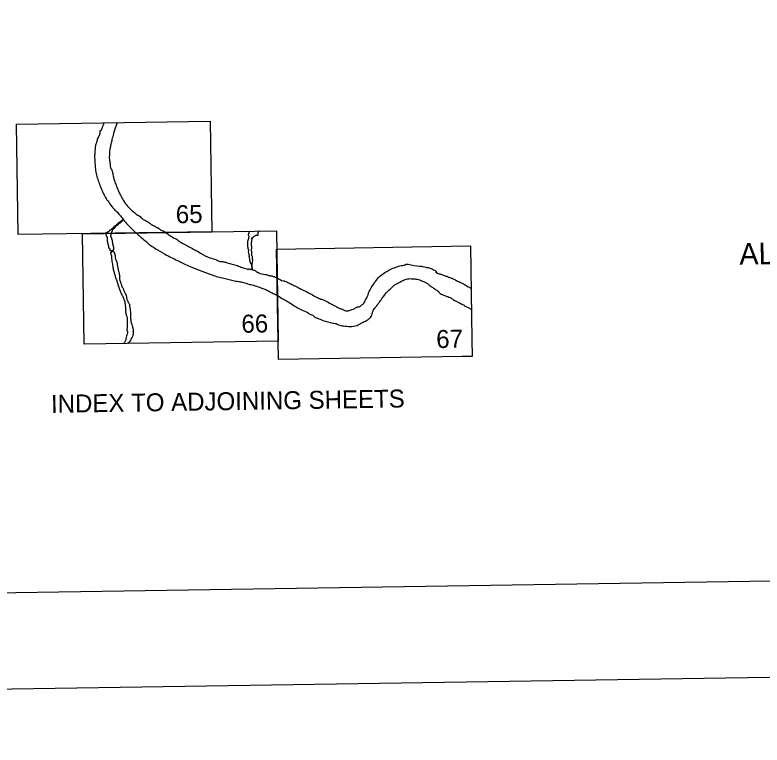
# Model space of a CAD drawing. Extents: x 3823584 to 3861785, y 301729 to 327625.
# Drawn here: x 3848300 to 3853151, y 302313 to 307056 of the extents above; entities that cross this region are included whole.
import ezdxf

# ---------------------------------------------------------------- set-up
doc = ezdxf.new("R2010")
doc.units = 0
for name, color, linetype in [('G-ANNO-NPLT', 7, 'Continuous'), ('V-ANNO-NPLT', 7, 'Continuous'), ('V-ANNO-SYMB', 7, 'Continuous'), ('V-ANNO-TEXT', 7, 'Continuous')]:
    doc.layers.add(name, color=color, linetype=linetype)

msp = doc.modelspace()

# ---------------------------------------------------------------- linework, layer by layer
at = {"layer": 'G-ANNO-NPLT'}
msp.add_lwpolyline([(3824539.5, 302312.7), (3861201.8, 302878), (3860829.2, 327041.8), (3824166.9, 326476.5)], close=True, dxfattribs=at)
at = {"layer": 'V-ANNO-NPLT'}
for points in [[(3848320, 305629), (3848309.4, 306347), (3849566.6, 306366.1), (3849577.8, 305648)], [(3849577.8, 305648), (3848320, 305629)], [(3848750, 304917.1), (3848739.2, 305635.2), (3849997, 305654.6), (3850008.4, 304936.5)], [(3850010.3, 304816.8), (3849998.9, 305534.9), (3851256.8, 305555.4), (3851267, 304947.3)], [(3850008.4, 304936.5), (3848750, 304917.1)], [(3851267, 304947.3), (3851268.8, 304837.3)], [(3851202.9, 304836.3), (3850010.3, 304816.8)], [(3851268.8, 304837.3), (3851202.9, 304836.3)]]:
    msp.add_lwpolyline(points, dxfattribs=at)
for points in [[(3848876.3, 306355.6), (3848870.6, 306335.7), (3848866.8, 306328.1), (3848859.7, 306307.2), (3848857.3, 306304.8), (3848853.5, 306303.3), (3848851.1, 306301), (3848850.2, 306293.3), (3848844, 306267.1), (3848841.6, 306263.3), (3848839.2, 306259), (3848831.1, 306233.3), (3848828.3, 306225.2)], [(3848963.6, 306356.9), (3848959.1, 306343.4), (3848950.6, 306321), (3848942.5, 306294.3), (3848932, 306254.7), (3848923.9, 306223.8), (3848921.6, 306213.3)], [(3848828.3, 306225.2), (3848824.5, 306216.1), (3848820.7, 306192.3), (3848818.7, 306154.7), (3848818.7, 306150.4)], [(3848921.8, 306214.5), (3848917.3, 306189.5), (3848915.4, 306181.8), (3848913.9, 306151.4)], [(3848835.4, 305996), (3848827.3, 306035.6), (3848823, 306073.7), (3848820.2, 306107), (3848818.7, 306150.4)], [(3848913.9, 306151.4), (3848913, 306117.5), (3848917.7, 306088.9), (3848923, 306058.4), (3848926.3, 306053.2), (3848934.9, 306026.5), (3848940.6, 305996.5)], [(3848835.4, 305996), (3848846.8, 305961.7), (3848861.1, 305924.6), (3848874.9, 305894.5), (3848892, 305863.6)], [(3848940.6, 305996.5), (3848947.7, 305972.2), (3848960.6, 305940.3), (3848972, 305911.2), (3848984.9, 305885), (3849002.9, 305853.1)], [(3848892, 305863.6), (3848913.9, 305832.1), (3848944.4, 305793.5), (3848964.9, 305774)], [(3849002.9, 305853.1), (3849018.2, 305828.8), (3849042.9, 305801.2), (3849066.7, 305778.8)], [(3848964.9, 305774), (3848984.9, 305750.2), (3849005.8, 305724.5), (3849031.5, 305694)], [(3849066.7, 305778.8), (3849088.6, 305759.7), (3849095.3, 305754.9), (3849097.6, 305754.9), (3849099.6, 305754.5), (3849123.3, 305735.9), (3849143.8, 305722.1), (3849161.9, 305712.5), (3849175.2, 305703)], [(3848934.8, 305670.7), (3848936.8, 305673.6), (3848940.6, 305676), (3848942.7, 305680.5), (3848945.1, 305682.6), (3848948.5, 305685.8), (3848950.9, 305687.3), (3848953.3, 305688.2), (3848956.2, 305689), (3848957.4, 305690.2), (3848959.6, 305693), (3848961, 305695), (3848963, 305697.1), (3848967.3, 305700.3), (3848969.2, 305703.1), (3848972.3, 305705.1), (3848974.7, 305707), (3848976.9, 305709.4), (3848980.5, 305711.3), (3848982.7, 305712.5), (3849001.8, 305729.3)], [(3848942.8, 305668.5), (3848945.4, 305671.9), (3848949.3, 305675.7), (3848951.7, 305678.8), (3848953.1, 305681.7), (3848956.5, 305685.1), (3848959.3, 305687.3), (3848962.1, 305689.5), (3848966.5, 305691.5), (3848969.4, 305693), (3848971.4, 305695.9), (3848972.6, 305698.8), (3848975.2, 305701.2), (3848976.2, 305701.9), (3848979.5, 305704.3), (3848982.7, 305706.5), (3848985.3, 305708), (3848987.5, 305709.2), (3849005.2, 305725.2)], [(3848901.7, 305647), (3848904.3, 305647.6), (3848909.6, 305650.5), (3848913.9, 305654.3), (3848917.1, 305657.7), (3848921.4, 305661.3), (3848926.2, 305663.9), (3848930.5, 305667.8), (3848933.2, 305669.5), (3848934.8, 305670.7)], [(3848930.9, 305595.6), (3848929.1, 305599), (3848928.6, 305601.6), (3848928.1, 305606.2), (3848927.4, 305608.4), (3848925.9, 305612), (3848924.5, 305614.6), (3848923.3, 305617.3), (3848923.1, 305622.1), (3848923.5, 305625.9), (3848923.5, 305628.8), (3848923.8, 305631.7), (3848923.8, 305631.9), (3848925.5, 305635.1), (3848928.1, 305639.4), (3848928.6, 305642.5), (3848928.4, 305643.7), (3848928.6, 305645.4), (3848930, 305646.9), (3848932, 305651.2), (3848932.4, 305655), (3848932.2, 305658.4), (3848933.9, 305659.8), (3848936, 305662.2), (3848938.2, 305664.7), (3848940.1, 305666.6), (3848942.8, 305668.5)], [(3849031.5, 305694), (3849055.3, 305670.1), (3849085.8, 305640.6)], [(3849175.2, 305703), (3849196.2, 305689.2), (3849199, 305688.2), (3849217.1, 305676.8), (3849223.8, 305673.5), (3849226.2, 305674), (3849232.3, 305671.1), (3849253.3, 305655.8), (3849261.4, 305653.5), (3849276.3, 305643.4)], [(3848899.9, 305593.2), (3848900.1, 305595.9), (3848899.9, 305597.3), (3848900.1, 305599.7), (3848900.8, 305602.3), (3848901.3, 305606.4), (3848900.1, 305612.5), (3848896.7, 305614.6), (3848895.5, 305617), (3848894.1, 305622.3), (3848893.1, 305625.9), (3848892.2, 305630), (3848893.1, 305631.7), (3848891.7, 305634.3), (3848890.7, 305635.8), (3848889.8, 305638.2), (3848891.9, 305641.1), (3848893.4, 305642.3), (3848897.7, 305644.4)], [(3848897.7, 305644.4), (3848901.2, 305646.9), (3848901.7, 305647)], [(3849085.8, 305640.6), (3849105.7, 305622.4), (3849135, 305598), (3849162.9, 305573.5), (3849190, 305552.6), (3849226.3, 305529.6), (3849284.9, 305496.1), (3849324.6, 305475.8), (3849365, 305456.3), (3849397.8, 305440.2), (3849436.8, 305422.8)], [(3849276.3, 305643.4), (3849298.8, 305627.3), (3849326.7, 305610.5), (3849354.6, 305594.5), (3849376.2, 305579.1), (3849411, 305560.3), (3849443.8, 305542.1), (3849475.2, 305526.8), (3849504.5, 305509.3)], [(3849819.9, 305613.9), (3849820, 305617.7), (3849817.9, 305623.3), (3849816.6, 305627.9), (3849817.1, 305631.9), (3849819, 305636.2), (3849820.3, 305638.7), (3849820.3, 305642.4), (3849820.3, 305646.2), (3849821.9, 305650.8), (3849822.4, 305651.8)], [(3849844.1, 305608.1), (3849845.8, 305610.7), (3849848.2, 305614.5), (3849851.7, 305616.4), (3849857.9, 305620.7), (3849862.5, 305624.1), (3849865.4, 305625.2), (3849868.4, 305626.6), (3849871.6, 305626), (3849875.4, 305626), (3849878.9, 305627.4), (3849879.7, 305629.8), (3849879.9, 305633.6), (3849879.1, 305637.3), (3849878.9, 305640.5), (3849880.2, 305644.8), (3849881.3, 305648.1), (3849883.7, 305650.2), (3849885.8, 305651.3), (3849888.4, 305652.8)], [(3848901.7, 305584.2), (3848900.8, 305589.4), (3848900.1, 305591.8), (3848899.9, 305593.2)], [(3848903.7, 305573.3), (3848902.8, 305576.8), (3848902, 305582.4), (3848901.7, 305584.2)], [(3848928.4, 305516.3), (3848928.2, 305519.4), (3848927.5, 305522.2), (3848926.3, 305523.9), (3848924.4, 305524.6), (3848922.2, 305524.4), (3848921.5, 305524.4), (3848920.5, 305524.4), (3848918.1, 305525.4), (3848917.4, 305526.1), (3848917.4, 305528.7), (3848917.7, 305532.1), (3848917.4, 305536), (3848914.5, 305537.6), (3848913.8, 305538.1), (3848912.4, 305539.6), (3848910.7, 305543.6), (3848909.5, 305548), (3848908.8, 305552.5), (3848907.8, 305558.6), (3848906.4, 305563.1), (3848905.4, 305567.7), (3848904.2, 305571.3), (3848903.7, 305573.3)], [(3848930.9, 305595.6), (3848931.6, 305593.4), (3848931.6, 305590.6), (3848930.2, 305588.2), (3848930.2, 305587), (3848931.6, 305582.9), (3848933, 305576.8), (3848933.7, 305573.3)], [(3848933.7, 305573.3), (3848934.2, 305570.1), (3848935.2, 305565.8), (3848935.9, 305560.2), (3848937.4, 305555), (3848939.5, 305548.9), (3848940, 305543.2), (3848939.5, 305539.3), (3848940, 305535), (3848939.8, 305531.1), (3848937.4, 305527.5), (3848933.8, 305526.3), (3848933, 305525.1), (3848932.8, 305524.4), (3848933.3, 305522.2), (3848934.5, 305520.1), (3848935.9, 305519.1), (3848936.1, 305519.1)], [(3849811.9, 305585.2), (3849812.4, 305588), (3849813.6, 305591.2), (3849815.1, 305595.1), (3849816.8, 305600.4), (3849818.9, 305605.4), (3849818.9, 305608.6), (3849818.9, 305611.9), (3849819.9, 305613.9)], [(3849814.6, 305536.7), (3849814.3, 305542.4), (3849812.6, 305546.8), (3849812.4, 305551.6), (3849812.6, 305558.4), (3849812.4, 305563.7), (3849812.2, 305569.9), (3849812.7, 305574.5), (3849812.7, 305577.7), (3849812.6, 305580.1), (3849812.2, 305583.5), (3849811.9, 305585.2)], [(3849835.6, 305584.4), (3849834.1, 305577.9), (3849833.4, 305570.2), (3849833.5, 305565.4), (3849834.1, 305560.3), (3849834.7, 305555), (3849835.1, 305549), (3849835.1, 305543.9), (3849835.3, 305540.3), (3849836.1, 305536.9)], [(3849844.1, 305608.1), (3849841.7, 305606.1), (3849838.5, 305605.9), (3849837.1, 305605.5), (3849836.8, 305605), (3849836.6, 305603.2), (3849837, 305602), (3849838, 305601.3), (3849837.5, 305599.2), (3849837.1, 305597.7), (3849836.3, 305595.3), (3849835.9, 305592.2), (3849836.3, 305589.5), (3849836.1, 305586.6), (3849835.6, 305584.4)], [(3848936.1, 305519.1), (3848939.3, 305519.4), (3848942.7, 305517.2), (3848943.8, 305513.3), (3848945.4, 305508.3), (3848947.1, 305504.4), (3848949.3, 305497.7), (3848950.4, 305492.1), (3848950.4, 305485.5), (3848951, 305481.6), (3848952.1, 305473.8), (3848954.9, 305466), (3848957.7, 305459.9), (3848962.1, 305449.8), (3848963.8, 305440.9), (3848964.3, 305433.7), (3848965.4, 305425.4), (3848967.7, 305415.4), (3848969.3, 305408.1), (3848971, 305398.7), (3848973.2, 305389.8), (3848976, 305380.3), (3848977.1, 305370.9), (3848978.2, 305364.7), (3848978.8, 305359.7), (3848979.9, 305354.7)], [(3849814.6, 305536.7), (3849815.5, 305529.4), (3849815.5, 305525.1), (3849816.5, 305507.5), (3849817.9, 305504.1), (3849818.5, 305500.9), (3849819.4, 305497), (3849820.2, 305493.4), (3849820.8, 305490), (3849821.3, 305487.2)], [(3849839.3, 305488.2), (3849838.7, 305492.2), (3849838.8, 305498.8), (3849838.8, 305505.5), (3849838.7, 305509.2), (3849838, 305515.7), (3849836.4, 305521), (3849835.9, 305525), (3849835.9, 305529.1), (3849835.6, 305533.5), (3849836.1, 305536.9)], [(3848950.4, 305365.3), (3848943.8, 305388.1), (3848938.2, 305414.2), (3848933.2, 305445.4), (3848930.4, 305463.2), (3848929.3, 305483.8), (3848927.1, 305496), (3848925.4, 305501), (3848923.2, 305504.9), (3848922.1, 305508.3), (3848921.5, 305509.9), (3848921.5, 305512.2), (3848922.7, 305513.8), (3848924.9, 305514.9), (3848927.7, 305516.1), (3848928.4, 305516.3)], [(3849504.5, 305509.3), (3849565.8, 305478.6), (3849607.6, 305465.4), (3849636.9, 305453.5), (3849648.8, 305453.5), (3849669, 305449.3), (3849702.5, 305438.8), (3849736.6, 305430.5), (3849767.3, 305417.9), (3849806.3, 305406.7)], [(3849832.7, 305440), (3849830.8, 305443.5), (3849829.5, 305446.6), (3849827.6, 305449.1), (3849827.1, 305455.3), (3849826.4, 305459.7), (3849825.4, 305463.8), (3849825, 305467.6), (3849823.7, 305475.6), (3849821.9, 305483.1), (3849821.3, 305487.2)], [(3849839.3, 305488.2), (3849839.9, 305478.5), (3849840.9, 305468.3), (3849841.6, 305465), (3849841.2, 305457.2), (3849840.2, 305449.1), (3849840.5, 305447.1), (3849841.1, 305445.2), (3849840.4, 305443.9), (3849839.7, 305442.8), (3849837.8, 305439.9), (3849836.9, 305438.1)], [(3849436.8, 305422.8), (3849502.4, 305394.9), (3849572.1, 305370.4), (3849607.6, 305357.9), (3849646.7, 305348.1), (3849682.2, 305339), (3849716.4, 305330.7), (3849752.7, 305324.4), (3849784, 305318.1)], [(3849832.8, 305439.8), (3849834.3, 305437.9), (3849835.9, 305432.8), (3849836.9, 305420.3), (3849836.9, 305412.4), (3849836.9, 305402.7)], [(3849836.9, 305438.1), (3849838.9, 305422.7), (3849839.6, 305402.1)], [(3850666.5, 305357.5), (3850701.1, 305382.3), (3850726.7, 305397.9), (3850763.2, 305414.2), (3850799, 305425.9), (3850817.6, 305429), (3850830.8, 305431.3), (3850840.9, 305436.8), (3850852.5, 305436), (3850927.1, 305424.3), (3850938.7, 305423.5), (3850948.8, 305421.2), (3850967.5, 305417.3), (3850974.5, 305415.8), (3850982.2, 305415), (3850994.7, 305411.1), (3851024.9, 305397.9)], [(3849806.3, 305406.7), (3849811.6, 305403.2), (3849815.1, 305403.9), (3849818.5, 305406), (3849824.8, 305405.3), (3849831.1, 305403.9), (3849836.9, 305402.7)], [(3849839.6, 305402.1), (3849840.9, 305401.8), (3849849.9, 305399), (3849855.5, 305397), (3849861.1, 305394.2), (3849863.9, 305391.4), (3849867.3, 305387.9), (3849872.2, 305385.1), (3849876.4, 305383), (3849882.7, 305380.9), (3849924.5, 305370.4), (3849929.4, 305370.4), (3849937.1, 305367.6), (3849957.3, 305362.1), (3849976.8, 305357.9), (3850001.9, 305348.5)], [(3851024.9, 305397.9), (3851031.9, 305392.4), (3851035, 305389.3), (3851034.3, 305386.2), (3851033.5, 305384.7), (3851033.5, 305383.1), (3851038.9, 305380.8), (3851042.8, 305379.2), (3851052.9, 305374.6), (3851063, 305373), (3851080.9, 305366), (3851093.3, 305360.6), (3851103.4, 305358.2), (3851113.5, 305353.6), (3851120.5, 305351.2), (3851124.4, 305350.5), (3851133.7, 305346.6), (3851139.9, 305343.5), (3851149.2, 305338.8), (3851160.9, 305334.1), (3851174.1, 305327.1), (3851188.8, 305320.1), (3851204.3, 305313.1), (3851212.1, 305308.5), (3851223.8, 305302.3), (3851237, 305293.7), (3851250.2, 305286.7), (3851260.3, 305278.9)], [(3848950.4, 305365.3), (3848951.6, 305357.5), (3848953.2, 305348.6), (3848958.2, 305336.9), (3848962.1, 305325.2), (3848965.4, 305313), (3848968.8, 305304.1), (3848972.7, 305293), (3848975.4, 305284.6), (3848978.2, 305275.2), (3848982.7, 305262.4), (3848986.6, 305252.9), (3848989.9, 305247.4), (3848992.7, 305241.8), (3848997.1, 305230.7), (3849002.7, 305221.2), (3849006, 305212.3), (3849009.3, 305204.5), (3849013.2, 305191.7), (3849013.2, 305184.5), (3849013.8, 305181.7), (3849017.1, 305176.1)], [(3848979.9, 305354.7), (3848978.2, 305344.7), (3848980.4, 305335.8), (3848982.7, 305326.3), (3848986.6, 305315.8), (3848989.9, 305308), (3848992.7, 305297.4), (3848994.3, 305290.7), (3848997.7, 305285.7), (3849002.1, 305278.5), (3849003.8, 305272.9), (3849006, 305266.8), (3849008.8, 305260.7), (3849012.1, 305254.6), (3849015.5, 305247.9), (3849018.2, 305241.2), (3849019.9, 305238.5), (3849022.7, 305231.2), (3849024.4, 305220.6), (3849025.5, 305212.9), (3849028.2, 305205.6), (3849032.1, 305197.3), (3849034.4, 305190.6), (3849037.1, 305185.6), (3849041, 305180), (3849042.7, 305177.3)], [(3850001.9, 305348.5), (3850042.2, 305328.7), (3850051.5, 305327.1), (3850077.9, 305315.5), (3850104.3, 305302.3), (3850131.5, 305289), (3850158.6, 305275.1), (3850190.5, 305258.7), (3850223.1, 305241.6), (3850258.1, 305223), (3850284.5, 305210.5), (3850307, 305203.5), (3850342.7, 305184.1), (3850372.2, 305168.5), (3850405.6, 305150.7), (3850414.9, 305146.8)], [(3850571.4, 305195.8), (3850591.2, 305233.9), (3850594.3, 305242.4), (3850595.1, 305250.2), (3850599, 305259.5), (3850626.9, 305304.6), (3850640.1, 305324.8), (3850666.5, 305357.5)], [(3850781.1, 305310.7), (3850798.2, 305320.1), (3850827.7, 305334.9), (3850840.9, 305339.6), (3850857.2, 305342.7), (3850875.1, 305342.7), (3850903, 305340.4), (3850920.9, 305336.5), (3850934.9, 305331.8), (3850958.2, 305322.5), (3850973.7, 305313.1), (3850989.2, 305303), (3851000.1, 305293.7), (3851008.6, 305287.5), (3851017.2, 305282.1), (3851027.3, 305275.1), (3851038.9, 305267.3)], [(3849784, 305318.1), (3849817.8, 305307.6), (3849846.4, 305300.6), (3849859.7, 305297.2), (3849896.6, 305283.2), (3849923.1, 305274.8), (3849934.3, 305269.2), (3849963.6, 305253.9), (3849990.7, 305240.5), (3850003.7, 305233)], [(3850641.3, 305157.7), (3850656.4, 305177.1), (3850668.9, 305194.2), (3850710.8, 305250.2), (3850721.7, 305262.6), (3850749.6, 305288.3), (3850769.1, 305305.4), (3850788.5, 305313.9)], [(3850003.7, 305233), (3850046.8, 305206.6), (3850077.1, 305189.5), (3850112.8, 305167), (3850165.6, 305139), (3850205.2, 305118.8), (3850209.9, 305114.9), (3850228.5, 305107.9), (3850237.1, 305102.5), (3850247.2, 305093.1), (3850264.3, 305086.1)], [(3851038.9, 305267.3), (3851049, 305259.5), (3851054.5, 305252.5), (3851061.4, 305245.5), (3851074.6, 305239.3), (3851091.7, 305233.1), (3851109.6, 305226.1), (3851125.9, 305219.9), (3851142.2, 305209), (3851166.3, 305195.8), (3851187.3, 305185.7), (3851211.3, 305172.4), (3851228.4, 305162.3), (3851247.8, 305153), (3851264.1, 305142.1)], [(3850571.4, 305195.8), (3850555.9, 305175.5), (3850547.3, 305168.5), (3850533.4, 305158.4), (3850524, 305157.7), (3850517.8, 305155.3), (3850500.7, 305145.2), (3850487.5, 305140.6), (3850480.5, 305139), (3850456.5, 305131.2), (3850439.4, 305135.1), (3850422.3, 305143.7), (3850414.9, 305146.8)], [(3849029.9, 305000.3), (3849029.4, 305006.5), (3849029.4, 305016.5), (3849029.9, 305024.8), (3849030.5, 305034.8), (3849031, 305043.7), (3849031, 305053.2), (3849031, 305065.4), (3849030.5, 305080.5), (3849029.9, 305088.2), (3849027.1, 305097.7), (3849024.4, 305105.5), (3849021, 305119.4), (3849020.5, 305131.1), (3849021, 305135.5), (3849020.5, 305141.1), (3849019.9, 305146.7), (3849019.3, 305153.3), (3849018.8, 305160), (3849018.2, 305167.2), (3849017.7, 305171.7), (3849017.1, 305176.1)], [(3849042.7, 305177.3), (3849043.2, 305169.5), (3849044.4, 305161.7), (3849046.6, 305153.9), (3849047.1, 305145.5), (3849048.2, 305135), (3849049.9, 305121.6), (3849050.5, 305102.7), (3849051, 305084.9), (3849052.1, 305069.3), (3849054.4, 305057.1), (3849057.7, 305047.6), (3849061.6, 305038.7), (3849063.8, 305027.6), (3849066.6, 305014.3), (3849067.7, 305004.8), (3849068.3, 305001.5)], [(3850264.3, 305086.1), (3850298.8, 305072.1), (3850363.3, 305054.3), (3850392.8, 305048), (3850401.3, 305043.4), (3850433.2, 305036.4), (3850475.1, 305032.5), (3850520.9, 305039.5), (3850552, 305055), (3850583.1, 305072.1), (3850601.7, 305084.6), (3850619.6, 305113.4), (3850622.7, 305128.9), (3850638.2, 305153.8), (3850641.3, 305157.7)], [(3849029.9, 305000.3), (3849029, 304982.9), (3849024.5, 304971), (3849016.3, 304936.7), (3849005.2, 304921.8), (3849004.5, 304921.1)], [(3849035, 304922.2), (3849044.6, 304932.2), (3849058, 304955.4), (3849067, 304973.3), (3849068.3, 305001.5)]]:
    msp.add_spline(points, degree=3, dxfattribs=at)
at = {"layer": 'V-ANNO-SYMB'}
msp.add_lwpolyline([(3827279.7, 302980), (3860358.9, 303490.1), (3860005.6, 326403.9), (3826926.4, 325893.9), (3827279.7, 302980)], dxfattribs=at)

# ---------------------------------------------------------------- texts
at = {"layer": 'V-ANNO-NPLT'}
for s, height, p in [('65', 117, (3849345, 305702.7)), ('66', 117, (3849771, 304991.1)), ('67', 117, (3851035.9, 304891.8)), ('INDEX TO ADJOINING SHEETS', 116.66, (3848534.8, 304470.8))]:
    msp.add_text(s, height=height, rotation=0.8834, dxfattribs=at).set_placement(p)
at = {"layer": 'V-ANNO-TEXT'}
msp.add_text('ALSO SOUTHWEST, SOUTH, AND PASS A LOUTRE.', height=140, rotation=1.0591, dxfattribs=at).set_placement((3853004.1, 305433.2))

doc.saveas('drawing.dxf')
